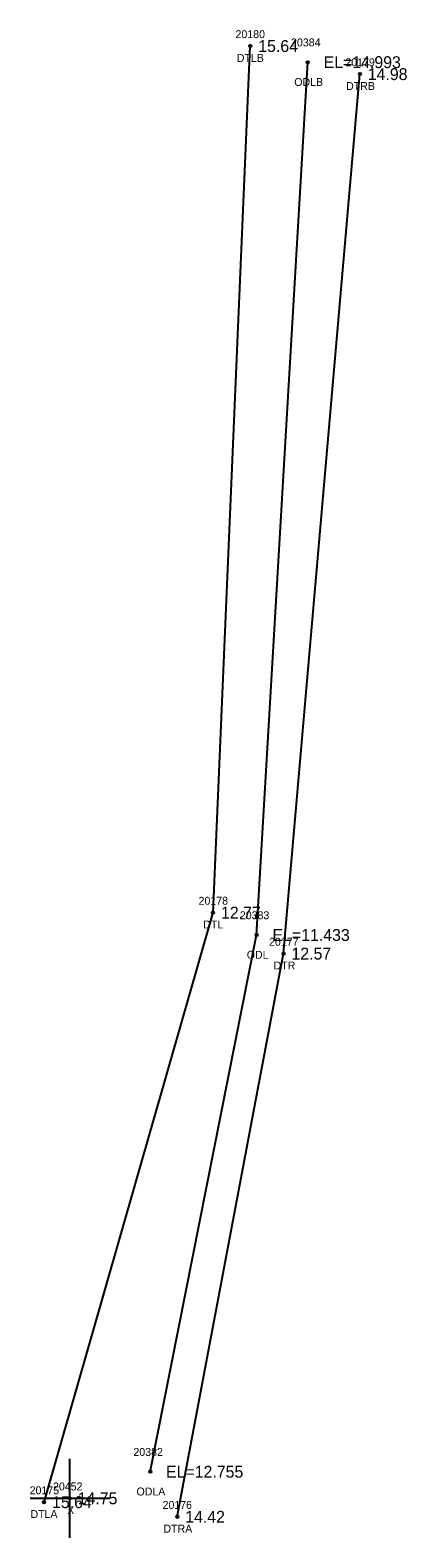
# Model space of a CAD drawing. Extents: x 2072302 to 2072980, y 127650 to 129736.
# Drawn here: x 2072664.8 to 2072712.3, y 129545.3 to 129735.9 of the extents above; entities that cross this region are included whole.
import ezdxf

# ---------------------------------------------------------------- set-up
doc = ezdxf.new("R2010")
doc.units = 0
for name, color, linetype in [('RD_EX_H2O', 7, 'Continuous'), ('RD_EX_H2O_txCode', 7, 'Continuous'), ('RD_EX_Misc', 7, 'Continuous'), ('RD_EX_Misc_txCode', 7, 'Continuous'), ('RD_EX_TX_H2O_ELEV', 7, 'Continuous'), ('RD_EX_TX_Misc_ELEV', 7, 'Continuous'), ('RD_SMD_Locator', 7, 'Continuous')]:
    doc.layers.add(name, color=color, linetype=linetype)

msp = doc.modelspace()

# ---------------------------------------------------------------- linework, layer by layer
at = {"layer": 'RD_EX_H2O'}
for points in [[(2072666.52, 129549.79), (2072687.87, 129624.32), (2072692.57, 129733.87)], [(2072679.92, 129553.64), (2072693.37, 129621.49), (2072699.83, 129731.83)], [(2072683.34, 129547.94), (2072696.77, 129619.14), (2072706.41, 129730.32)]]:
    msp.add_lwpolyline(points, dxfattribs=at)
at = {"layer": 'RD_EX_Misc'}
for p, q in [((2072669.76, 129545.28), (2072669.76, 129555.28)), ((2072664.76, 129550.28), (2072674.76, 129550.28))]:
    msp.add_line(p, q, dxfattribs=at)
at = {"layer": 'RD_SMD_Locator'}
for centre in [(2072692.57, 129733.87), (2072699.83, 129731.83), (2072706.41, 129730.32), (2072687.87, 129624.32), (2072693.37, 129621.49), (2072696.77, 129619.14), (2072679.92, 129553.64), (2072666.52, 129549.79), (2072669.76, 129550.28), (2072683.34, 129547.94)]:
    msp.add_circle(centre, 0.15, dxfattribs=at)

# ---------------------------------------------------------------- texts
at = {"layer": 'RD_EX_H2O_txCode'}
for s, p in [('20180', (2072690.7, 129734.87)), ('20384', (2072697.72, 129733.83)), ('DTLB', (2072690.86, 129731.87)), ('20179', (2072704.58, 129731.32)), ('ODLB', (2072698.12, 129728.83)), ('DTRB', (2072704.67, 129728.32)), ('20178', (2072686.03, 129625.32)), ('20383', (2072691.25, 129623.49)), ('DTL', (2072686.62, 129622.32)), ('20177', (2072694.94, 129620.14)), ('ODL', (2072692.12, 129618.49)), ('DTR', (2072695.51, 129617.14)), ('20382', (2072677.8, 129555.64)), ('20175', (2072664.69, 129550.79)), ('ODLA', (2072678.19, 129550.64)), ('20176', (2072681.48, 129548.94)), ('DTLA', (2072664.79, 129547.79)), ('DTRA', (2072681.59, 129545.94))]:
    msp.add_text(s, height=1, dxfattribs=at).set_placement(p)
at = {"layer": 'RD_EX_Misc_txCode'}
for s, p in [('20452', (2072667.64, 129551.28)), ('X', (2072669.44, 129548.28))]:
    msp.add_text(s, height=1, dxfattribs=at).set_placement(p)
at = {"layer": 'RD_EX_TX_H2O_ELEV'}
for s, p in [('15.64', (2072693.57, 129733.12)), ('EL=14.993', (2072701.83, 129731.08)), ('14.98', (2072707.41, 129729.57)), ('12.77', (2072688.87, 129623.57)), ('EL=11.433', (2072695.37, 129620.74)), ('12.57', (2072697.77, 129618.39)), ('EL=12.755', (2072681.92, 129552.89)), ('15.64', (2072667.52, 129549.04)), ('14.42', (2072684.34, 129547.19))]:
    msp.add_text(s, height=1.5, dxfattribs=at).set_placement(p)
at = {"layer": 'RD_EX_TX_Misc_ELEV'}
msp.add_text('14.75', height=1.5, dxfattribs=at).set_placement((2072670.76, 129549.53))

doc.saveas('drawing.dxf')
